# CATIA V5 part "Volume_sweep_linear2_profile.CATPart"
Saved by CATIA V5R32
Part number: Part1
Bounding box of the stored display mesh (mm): x -59.804 to 154.398, y 1.869 to 39.866, z 0 to 157
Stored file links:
  D:\PROJECTS\Project 2022\CATIA V5 6R 2022\Resources\Part Files\c17_catia_v6_6r2022_prt\Volume_sweep_linear2_profile.CATPart
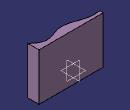
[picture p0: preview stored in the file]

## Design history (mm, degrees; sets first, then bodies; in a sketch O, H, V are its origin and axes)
Set1
  Sketch1 on xy-plane, origin (0, 0, 0), H (1, 0, 0), V (0, 1, 0)
    spline S1 through (154.3979, 1.8689) (93.1563, 21.7077) (57.7914, 10.782) (13.5134, 17.6824) (-59.804, 28.3207)
  Extrude1: Element1 Sketch1, Lim1 157, Lim2 0
  Sweep1: type Segment, GuideCrv Extrude1, Length1 10, Length2 0, Angle 0, DraftDirection zx-plane
Body1 (main body)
